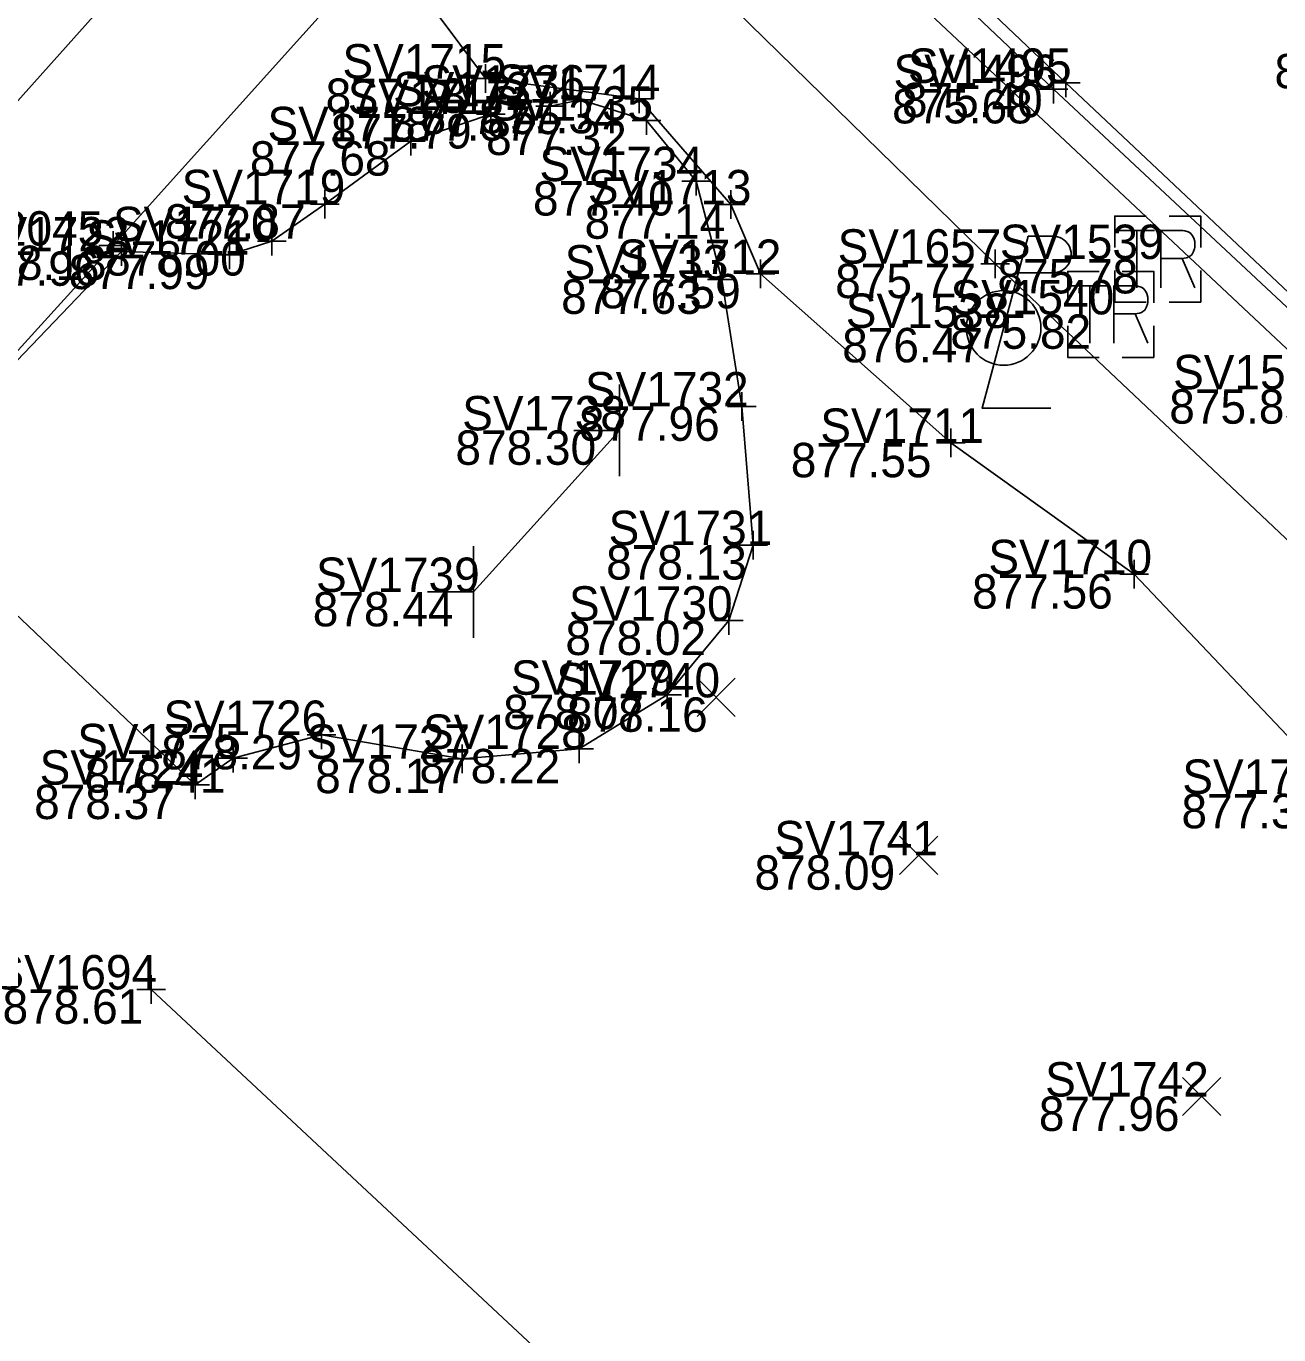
# Model space of a CAD drawing. Extents: x 1480001 to 1480402, y 379235 to 379603.
# Drawn here: x 1480179.61 to 1480223.31, y 379312.62 to 379358.27 of the extents above; entities that cross this region are included whole.
import ezdxf

# ---------------------------------------------------------------- set-up
doc = ezdxf.new("R2010")
doc.units = 0
for name, color, linetype in [('BD_X_Building', 7, 'Continuous'), ('Default', 7, 'Continuous'), ('PV_X_Curb', 7, 'Continuous'), ('PV_X_Walk', 7, 'Continuous'), ('SG_X_PullBox', 7, 'Continuous'), ('SN_X_Public', 7, 'Continuous'), ('SV_X_Break_Lines', 7, 'Continuous'), ('SV_X_Random_Point', 7, 'Continuous'), ('SV_X_Shot_Marker', 7, 'Continuous'), ('SV_X_Text_Elevation', 7, 'Continuous'), ('SV_X_Text_Name', 7, 'Continuous'), ('UT_X_Misc_Cells', 7, 'Continuous'), ('UT_X_Water', 7, 'Continuous'), ('VG_X_Flower_Bed', 7, 'Continuous')]:
    doc.layers.add(name, color=color, linetype=linetype)

msp = doc.modelspace()

# ---------------------------------------------------------------- linework, layer by layer
at = {"layer": 'BD_X_Building'}
msp.add_line((1480183.972, 379324.669), (1480206.583, 379303.558), dxfattribs=at)
at = {"layer": 'Default'}
msp.add_line((1480200.308, 379344.167), (1480195.208, 379338.532), dxfattribs=at)
at = {"layer": 'PV_X_Curb'}
for points in [[(1480233.83, 379339.39), (1480215.875, 379356.288), (1480200.731, 379370.664), (1480190.903, 379379.712), (1480187.53, 379382.642), (1480185.615, 379384.173), (1480181.928, 379385.583), (1480179.411, 379386.173), (1480174.793, 379387.235), (1480172.715, 379387.432), (1480170.332, 379387.359), (1480168.876, 379387.382), (1480166.808, 379386.944), (1480164.881, 379386.368), (1480162.883, 379385.531), (1480159.898, 379383.853), (1480158.052, 379382.754), (1480156.183, 379381.403), (1480155.05, 379380.342)], [(1480233.297, 379339.4), (1480215.447, 379356.074), (1480200.436, 379370.31), (1480191.889, 379378.223), (1480190.185, 379379.842), (1480188.303, 379381.604), (1480185.259, 379383.605), (1480181.861, 379385.001), (1480179.101, 379385.902), (1480178.705, 379386.045), (1480178.118, 379386.223), (1480177.29, 379386.43), (1480176.688, 379386.511), (1480174.95, 379386.851), (1480173.419, 379387.005), (1480171.202, 379387.128), (1480169.933, 379386.966), (1480168.123, 379386.781), (1480166.87, 379386.446), (1480165.488, 379386.008), (1480163.201, 379385.04), (1480160.165, 379383.332), (1480157.23, 379381.331), (1480156.058, 379380.439)]]:
    msp.add_lwpolyline(points, dxfattribs=at)
at = {"layer": 'PV_X_Walk'}
for points in [[(1480327.959, 379242.083), (1480313.163, 379256.356), (1480297.576, 379270.674), (1480283.951, 379284.205), (1480267.344, 379299.69), (1480258.509, 379307.782), (1480244.036, 379321.372), (1480229.243, 379335.021), (1480213.414, 379349.982), (1480196.806, 379366.202), (1480192.296, 379370.271), (1480186.385, 379375.802), (1480181.8, 379379.27), (1480179.258, 379381.212), (1480177.445, 379382.131), (1480174.921, 379382.868), (1480171.98, 379383.537), (1480169.491, 379383.403), (1480167.014, 379382.902), (1480162.891, 379380.83), (1480161.298, 379379.691), (1480158.915, 379377.808)], [(1480108.223, 379298.793), (1480126.311, 379318.205), (1480145.385, 379338.742), (1480160.312, 379354.639), (1480170.225, 379345.82), (1480179.011, 379355.326), (1480188.24, 379365.647)], [(1480192.517, 379361.591), (1480182.642, 379350.612), (1480174.641, 379341.817)]]:
    msp.add_lwpolyline(points, dxfattribs=at)
at = {"layer": 'SG_X_PullBox'}
for p, q in [((1480219.083, 379350.144), (1480219.083, 379350.144)), ((1480217.444, 379348.213), (1480217.444, 379348.213))]:
    msp.add_line(p, q, dxfattribs=at)
for points in [[(1480218.683, 379351.644), (1480217.583, 379351.644), (1480217.583, 379350.544)], [(1480220.583, 379350.544), (1480220.583, 379351.644), (1480219.483, 379351.644)], [(1480217.727, 379351.144), (1480218.971, 379351.144)], [(1480218.357, 379351.144), (1480218.357, 379349.144)], [(1480219.195, 379349.144), (1480219.195, 379351.144), (1480219.951, 379351.144), (1480220.029, 379351.128), (1480220.14, 379351.097), (1480220.187, 379351.065), (1480220.234, 379351.034), (1480220.297, 379350.955), (1480220.344, 379350.876), (1480220.376, 379350.751), (1480220.376, 379350.562), (1480220.36, 379350.499), (1480220.329, 379350.404), (1480220.266, 379350.294), (1480220.203, 379350.247), (1480220.155, 379350.215), (1480220.124, 379350.199), (1480220.077, 379350.184), (1480219.935, 379350.168), (1480219.195, 379350.168)], [(1480219.935, 379350.168), (1480220.376, 379349.144)], [(1480217.044, 379349.713), (1480215.944, 379349.713), (1480215.944, 379348.613)], [(1480217.583, 379349.744), (1480217.583, 379348.644), (1480218.683, 379348.644)], [(1480218.944, 379348.613), (1480218.944, 379349.713), (1480217.844, 379349.713)], [(1480219.483, 379348.644), (1480220.583, 379348.644), (1480220.583, 379349.744)], [(1480216.088, 379349.213), (1480217.332, 379349.213)], [(1480216.718, 379349.213), (1480216.718, 379347.213)], [(1480217.556, 379347.213), (1480217.556, 379349.213), (1480218.312, 379349.213), (1480218.39, 379349.197), (1480218.501, 379349.166), (1480218.548, 379349.134), (1480218.595, 379349.103), (1480218.658, 379349.024), (1480218.705, 379348.945), (1480218.737, 379348.819), (1480218.737, 379348.63), (1480218.721, 379348.567), (1480218.69, 379348.473), (1480218.627, 379348.363), (1480218.564, 379348.316), (1480218.516, 379348.284), (1480218.485, 379348.268), (1480218.438, 379348.253), (1480218.296, 379348.237), (1480217.556, 379348.237)], [(1480218.296, 379348.237), (1480218.737, 379347.213)], [(1480215.944, 379347.813), (1480215.944, 379346.713), (1480217.044, 379346.713)], [(1480217.844, 379346.713), (1480218.944, 379346.713), (1480218.944, 379347.813)]]:
    msp.add_lwpolyline(points, dxfattribs=at)
at = {"layer": 'SN_X_Public'}
for p, q in [((1480200.308, 379345.767), (1480200.308, 379342.567)), ((1480200.308, 379344.167), (1480198.708, 379344.167)), ((1480195.208, 379340.132), (1480195.208, 379336.932)), ((1480195.208, 379338.532), (1480193.608, 379338.532))]:
    msp.add_line(p, q, dxfattribs=at)
at = {"layer": 'SV_X_Break_Lines'}
msp.add_lwpolyline([(1480230.882, 379325.878), (1480225.522, 379331.489), (1480218.264, 379339.152), (1480211.865, 379343.732), (1480205.22, 379349.624), (1480204.187, 379352.051), (1480200.993, 379355.729), (1480195.628, 379356.44), (1480192.91, 379360.091)], dxfattribs=at)
at = {"layer": 'SV_X_Random_Point'}
for p, q in [((1480203.011, 379334.187), (1480204.345, 379335.522)), ((1480203.011, 379335.522), (1480204.345, 379334.187)), ((1480210.073, 379328.679), (1480211.407, 379330.014)), ((1480210.073, 379330.014), (1480211.407, 379328.679)), ((1480219.946, 379320.266), (1480221.28, 379321.601)), ((1480219.946, 379321.601), (1480221.28, 379320.266))]:
    msp.add_line(p, q, dxfattribs=at)
at = {"layer": 'SV_X_Shot_Marker'}
for p, q in [((1480195.628, 379356.94), (1480195.628, 379355.94)), ((1480215.447, 379356.574), (1480215.447, 379355.574)), ((1480215.875, 379356.788), (1480215.875, 379355.788)), ((1480195.128, 379356.44), (1480196.128, 379356.44)), ((1480195.628, 379356.44), (1480195.628, 379356.44)), ((1480198.952, 379356.201), (1480198.952, 379355.201)), ((1480200.993, 379356.229), (1480200.993, 379355.229)), ((1480214.947, 379356.074), (1480215.947, 379356.074)), ((1480215.375, 379356.288), (1480216.375, 379356.288)), ((1480215.447, 379356.074), (1480215.447, 379356.074)), ((1480215.875, 379356.288), (1480215.875, 379356.288)), ((1480195.813, 379355.699), (1480195.813, 379354.699)), ((1480197.886, 379355.971), (1480197.886, 379354.971)), ((1480198.452, 379355.701), (1480199.452, 379355.701)), ((1480198.952, 379355.701), (1480198.952, 379355.701)), ((1480200.493, 379355.729), (1480201.493, 379355.729)), ((1480200.993, 379355.729), (1480200.993, 379355.729)), ((1480195.313, 379355.199), (1480196.313, 379355.199)), ((1480195.813, 379355.199), (1480195.813, 379355.199)), ((1480197.386, 379355.471), (1480198.386, 379355.471)), ((1480197.886, 379355.471), (1480197.886, 379355.471)), ((1480201.244, 379355.471), (1480201.244, 379354.471)), ((1480193.023, 379354.753), (1480193.023, 379353.753)), ((1480200.744, 379354.971), (1480201.744, 379354.971)), ((1480201.244, 379354.971), (1480201.244, 379354.971)), ((1480192.523, 379354.253), (1480193.523, 379354.253)), ((1480193.023, 379354.253), (1480193.023, 379354.253)), ((1480202.983, 379353.361), (1480202.983, 379352.361)), ((1480202.483, 379352.861), (1480203.483, 379352.861)), ((1480202.983, 379352.861), (1480202.983, 379352.861)), ((1480190.027, 379352.557), (1480190.027, 379351.557)), ((1480204.187, 379352.551), (1480204.187, 379351.551)), ((1480189.527, 379352.057), (1480190.527, 379352.057)), ((1480190.027, 379352.057), (1480190.027, 379352.057)), ((1480203.687, 379352.051), (1480204.687, 379352.051)), ((1480204.187, 379352.051), (1480204.187, 379352.051)), ((1480182.642, 379351.112), (1480182.642, 379350.112)), ((1480188.179, 379351.267), (1480188.179, 379350.267)), ((1480182.142, 379350.612), (1480183.142, 379350.612)), ((1480182.642, 379350.612), (1480182.642, 379350.612)), ((1480182.933, 379350.911), (1480182.933, 379349.911)), ((1480186.704, 379350.796), (1480186.704, 379349.796)), ((1480187.679, 379350.767), (1480188.679, 379350.767)), ((1480188.179, 379350.767), (1480188.179, 379350.767)), ((1480182.433, 379350.411), (1480183.433, 379350.411)), ((1480182.933, 379350.411), (1480182.933, 379350.411)), ((1480186.204, 379350.296), (1480187.204, 379350.296)), ((1480186.704, 379350.296), (1480186.704, 379350.296)), ((1480205.22, 379350.124), (1480205.22, 379349.124)), ((1480213.414, 379350.482), (1480213.414, 379349.482)), ((1480203.872, 379349.931), (1480203.872, 379348.931)), ((1480212.914, 379349.982), (1480213.914, 379349.982)), ((1480213.414, 379349.982), (1480213.414, 379349.982)), ((1480203.372, 379349.431), (1480204.372, 379349.431)), ((1480203.872, 379349.431), (1480203.872, 379349.431)), ((1480204.72, 379349.624), (1480205.72, 379349.624)), ((1480205.22, 379349.624), (1480205.22, 379349.624)), ((1480204.571, 379345.503), (1480204.571, 379344.503)), ((1480204.071, 379345.003), (1480205.071, 379345.003)), ((1480204.571, 379345.003), (1480204.571, 379345.003)), ((1480211.865, 379344.232), (1480211.865, 379343.232)), ((1480211.365, 379343.732), (1480212.365, 379343.732)), ((1480211.865, 379343.732), (1480211.865, 379343.732)), ((1480204.97, 379340.665), (1480204.97, 379339.665)), ((1480204.47, 379340.165), (1480205.47, 379340.165)), ((1480204.97, 379340.165), (1480204.97, 379340.165)), ((1480218.264, 379339.652), (1480218.264, 379338.652)), ((1480217.764, 379339.152), (1480218.764, 379339.152)), ((1480218.264, 379339.152), (1480218.264, 379339.152)), ((1480204.125, 379338.031), (1480204.125, 379337.031)), ((1480203.625, 379337.531), (1480204.625, 379337.531)), ((1480204.125, 379337.531), (1480204.125, 379337.531)), ((1480201.966, 379335.447), (1480201.966, 379334.447)), ((1480201.466, 379334.947), (1480202.466, 379334.947)), ((1480201.966, 379334.947), (1480201.966, 379334.947)), ((1480189.913, 379334.045), (1480189.913, 379333.045)), ((1480186.83, 379333.232), (1480186.83, 379332.232)), ((1480189.413, 379333.545), (1480190.413, 379333.545)), ((1480189.913, 379333.545), (1480189.913, 379333.545)), ((1480198.902, 379333.557), (1480198.902, 379332.557)), ((1480194.82, 379333.214), (1480194.82, 379332.214)), ((1480198.402, 379333.057), (1480199.402, 379333.057)), ((1480198.902, 379333.057), (1480198.902, 379333.057)), ((1480186.33, 379332.732), (1480187.33, 379332.732)), ((1480186.83, 379332.732), (1480186.83, 379332.732)), ((1480194.32, 379332.714), (1480195.32, 379332.714)), ((1480194.82, 379332.714), (1480194.82, 379332.714)), ((1480185.507, 379332.31), (1480185.507, 379331.31)), ((1480185.007, 379331.81), (1480186.007, 379331.81)), ((1480185.507, 379331.81), (1480185.507, 379331.81)), ((1480183.972, 379325.169), (1480183.972, 379324.169)), ((1480183.472, 379324.669), (1480184.472, 379324.669)), ((1480183.972, 379324.669), (1480183.972, 379324.669))]:
    msp.add_line(p, q, dxfattribs=at)
at = {"layer": 'UT_X_Misc_Cells'}
for p, q in [((1480214.563, 379350.941), (1480215.413, 379350.941)), ((1480214.221, 379349.666), (1480215.413, 379349.666))]:
    msp.add_line(p, q, dxfattribs=at)
msp.add_lwpolyline([(1480214.563, 379350.941), (1480212.956, 379344.941), (1480215.356, 379344.941)], dxfattribs=at)
msp.add_circle((1480213.706, 379347.741), 1.3, dxfattribs=at)
msp.add_arc((1480215.425, 379350.303), 0.638, 268.8767, 91.1233, dxfattribs=at)
at = {"layer": 'UT_X_Water'}
msp.add_lwpolyline([(1480225.088, 379345.601), (1480208.322, 379361.342), (1480207.346, 379362.25), (1480199.528, 379369.768), (1480193.21, 379375.651), (1480182.823, 379385.139), (1480177.927, 379389.525), (1480169.423, 379398.321), (1480161.035, 379406.189), (1480144.924, 379421.019), (1480134.739, 379430.559), (1480121.485, 379441.998), (1480113.085, 379450.369), (1480106.418, 379456.915), (1480094.539, 379467.985), (1480089.15, 379472.551), (1480086.751, 379474.713), (1480073.459, 379487.337), (1480068.123, 379493.187), (1480050.678, 379510.207), (1480044.404, 379515.873)], dxfattribs=at)
at = {"layer": 'VG_X_Flower_Bed'}
msp.add_lwpolyline([(1480195.813, 379355.199), (1480193.023, 379354.253), (1480190.027, 379352.057), (1480188.179, 379350.767), (1480186.704, 379350.296), (1480182.933, 379350.411), (1480174.831, 379341.95), (1480185.507, 379331.81), (1480186.83, 379332.732), (1480189.913, 379333.545), (1480194.82, 379332.714), (1480198.902, 379333.057), (1480201.966, 379334.947), (1480204.125, 379337.531), (1480204.97, 379340.165), (1480204.571, 379345.003), (1480203.872, 379349.431), (1480202.983, 379352.861), (1480201.244, 379354.971), (1480198.952, 379355.701), (1480197.886, 379355.471)], dxfattribs=at)

# ---------------------------------------------------------------- texts
at = {"layer": 'SV_X_Text_Elevation'}
for s, p in [('875.72', (1480223.156, 379356.097)), ('877.78', (1480190.054, 379355.24)), ('875.68', (1480209.816, 379354.874)), ('875.40', (1480210.159, 379355.088)), ('877.55', (1480193.368, 379354.501)), ('877.34', (1480195.4, 379354.529)), ('877.79', (1480190.239, 379353.999)), ('877.57', (1480192.302, 379354.271)), ('877.32', (1480195.651, 379353.771)), ('877.68', (1480187.411, 379353.053)), ('877.40', (1480197.286, 379351.661)), ('877.87', (1480184.443, 379350.857)), ('877.14', (1480199.086, 379350.851)), ('878.18', (1480177.502, 379349.412)), ('878.00', (1480182.359, 379349.567)), ('877.96', (1480177.255, 379349.211)), ('877.99', (1480181.092, 379349.096)), ('875.78', (1480213.49, 379348.944)), ('875.77', (1480207.83, 379348.782)), ('877.63', (1480198.269, 379348.231)), ('877.59', (1480199.627, 379348.424)), ('875.82', (1480211.851, 379347.013)), ('876.47', (1480208.075, 379346.541)), ('875.85', (1480219.485, 379344.401)), ('877.96', (1480198.893, 379343.803)), ('878.30', (1480194.582, 379342.967)), ('877.55', (1480206.281, 379342.532)), ('878.13', (1480199.84, 379338.965)), ('877.56', (1480212.605, 379337.952)), ('878.44', (1480189.605, 379337.332)), ('878.02', (1480198.418, 379336.331)), ('878.07', (1480196.25, 379333.747)), ('878.16', (1480198.473, 379333.655)), ('878.29', (1480184.32, 379332.345)), ('878.22', (1480193.328, 379331.857)), ('878.41', (1480181.652, 379331.532)), ('878.17', (1480189.69, 379331.514)), ('878.37', (1480179.885, 379330.61)), ('877.39', (1480219.91, 379330.289)), ('878.09', (1480205.014, 379328.146)), ('878.61', (1480178.784, 379323.469)), ('877.96', (1480214.935, 379319.733))]:
    msp.add_text(s, height=1.2, dxfattribs=at).set_placement(p)
at = {"layer": 'SV_X_Text_Name'}
for s, p in [('SV1715', (1480190.641, 379356.44)), ('SV1495', (1480210.367, 379356.288)), ('SV1496', (1480209.864, 379356.074)), ('SV1737', (1480192.407, 379355.471)), ('SV1736', (1480193.397, 379355.701)), ('SV1714', (1480196.015, 379355.729)), ('SV1717', (1480190.826, 379355.199)), ('SV1735', (1480195.765, 379354.971)), ('SV1718', (1480188.026, 379354.253)), ('SV1734', (1480197.513, 379352.861)), ('SV1719', (1480185.03, 379352.057)), ('SV1713', (1480199.2, 379352.051)), ('SV1720', (1480182.634, 379350.767)), ('SA2045', (1480176.585, 379350.612)), ('SV1722', (1480177.501, 379350.411)), ('SV1721', (1480181.696, 379350.296)), ('SV1657', (1480207.916, 379349.982)), ('SV1539', (1480213.575, 379350.144)), ('SV1733', (1480198.393, 379349.431)), ('SV1712', (1480200.242, 379349.624)), ('SV1540', (1480211.851, 379348.213)), ('SV1538', (1480208.198, 379347.741)), ('SV1552', (1480219.618, 379345.601)), ('SV1732', (1480199.101, 379345.003)), ('SV1738', (1480194.819, 379344.167)), ('SV1711', (1480207.311, 379343.732)), ('SV1731', (1480199.925, 379340.165)), ('SV1710', (1480213.173, 379339.152)), ('SV1739', (1480189.719, 379338.532)), ('SV1730', (1480198.542, 379337.531)), ('SV1729', (1480196.515, 379334.947)), ('SV1740', (1480198.104, 379334.855)), ('SV1726', (1480184.396, 379333.545)), ('SV1728', (1480193.451, 379333.057)), ('SV1725', (1480181.389, 379332.732)), ('SV1727', (1480189.379, 379332.714)), ('SV1724', (1480180.075, 379331.81)), ('SV1709', (1480219.939, 379331.489)), ('SV1741', (1480205.704, 379329.346)), ('SV1694', (1480178.464, 379324.669)), ('SV1742', (1480215.153, 379320.933))]:
    msp.add_text(s, height=1.2, dxfattribs=at).set_placement(p)

doc.saveas('drawing.dxf')
